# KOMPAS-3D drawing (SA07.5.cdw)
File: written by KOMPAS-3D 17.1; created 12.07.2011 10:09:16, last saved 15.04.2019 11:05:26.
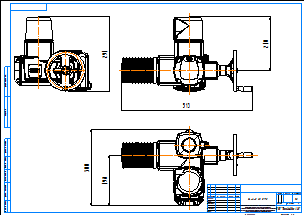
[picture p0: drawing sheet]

Title block, sheet 1: name: Привод SA 07.5; material: Внимание! Данный продукт является объектом авторского права ООО «Торговый Дом АДЛ». / Запрещается изменение, копирование, распространение / (в том числе путем копирования на другие сайты и ресурсы в Интернете) / или любое иное использование информации и объектов без предварительного / согласия правообладателя (ООО «Торговый Дом АДЛ»).; scale: 1:2; sheets: 1; organisation: ООО "Торговый дом АДЛ"; sheet format: A2; stored path: \\adlc.lan\data\АДЛ_ПКД\3D-модели\Поставщики\Сервоприводы AUMA\Электроприводы серии SA\KOMPAS 2D\Привод SA 07.5.cdw

Views: Проекционный вид 2, Проекционный вид 4, Проекционный вид 6
Dimensions and other numbers on the sheet: 300; 198; 291; 210; 513; 1:2; 1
